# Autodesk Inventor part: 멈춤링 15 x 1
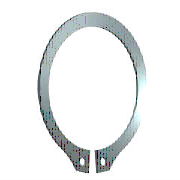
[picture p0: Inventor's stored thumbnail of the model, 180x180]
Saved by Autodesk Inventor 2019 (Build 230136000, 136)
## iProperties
IsCustomPart: 1
Created: 2012-02
Part Number: 멈춤링 15 x 1
Material: 강철, 연강
Description: 리테이닝 링(C형)
Document SubType Name: Modeling
Standard: KS B 1336
Designer: mduedu
Standards Organization: KS
Language: ko-KR
Size Designation: 15 x 1
Categories: <MemberInstance><Categories><Category DisplayName="샤프트 부품" InternalName="7f7aeb1f-a693-4053-b835-cee3144e0d98" Mnemonic="SHFT"><Category DisplayName="써클립" Inter
Density: 1 g/cm^3
Appearance: 파란색 - 벽 페인트 - 광택
Author: mduedu
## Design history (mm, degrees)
sketch "스케치1"
  geometry: L1 (-6, 0)-(6, 0) reference; L2 (0, 20.189)-(0, -80.536) reference; L3 (-48.09, 0)-(48.09, 0) reference; L4 (-0.425, -14.637)-(-0.425, -18.137); L5 (-0.425, -6.54)-(-0.425, -13.29); L6 (-2.795, 2.1)-(3.672, 2.1); L7 (0.425, -6.54)-(0.425, -13.29); L8 (0.425, -14.637)-(0.425, -18.137); C1 r 0.85 at (-1.7, -16.283); C2 r 0.85 at (1.7, -16.283); A1 r 7.15 centre (0, -7.5) between (0.425, -14.637) and (-0.425, -14.637); A2 r 9.075 centre (0, -6.975) between (4.291, -14.971) and (-4.291, -14.971); A3 r 10.646 centre (0, -7.5) between (-2.023, -17.952) and (-0.425, -18.137); A4 r 1.7 centre (-1.7, -16.283) between (-3.397, -16.376) and (-2.023, -17.952); A5 r 1.7 centre (-5.095, -16.469) between (-3.397, -16.376) and (-4.291, -14.971); A6 r 1.7 centre (5.095, -16.469) between (4.291, -14.971) and (3.397, -16.376); A7 r 1.7 centre (1.7, -16.283) between (2.023, -17.952) and (3.397, -16.376); A8 r 10.646 centre (0, -7.5) between (0.425, -18.137) and (2.023, -17.952)
  constraints: 16 point on circle, 12 end point, 10 centre point, 9 symmetric about line, 5 point on line, 4 tangent, 3 coincident, 2 horizontal, 1 perpendicular, 1 vertical, 5 other
  dimensions: "d0" = 14.3 diameter of A1 (= ND); "d1" = 3.5 distance of L4.end L4.start (= SRB2); "d6" = 0.425 distance between parallel lines of L2 L5 (= 0.25 x SD5); "d7" = 2.1 distance between parallel lines of L6 L3 (= SRB1); "d8" = 0.525 distance of A1.centre A2.centre (= 0.25 x SRB1); "d9" = 1.7 radius of A4 (= SD5); "d10" = 1.7 radius of A5 (= SD5); "d11" = 1.275 distance from line of L4 A4.centre (= 0.75 x SD5); "d12" = 1.7 diameter of C1 (= SD5); "d13" = 1.7 diameter of C2 (= SD5); "d14" = 7.5 distance from line of A1.centre L1 (= 0.5 x WD)
extrude "본체" new body sketch "스케치1" distance "d2" = 1 (= SD); taper "d3" = 0 deg
workaxis "Work Axis1"
workplane "Work Plane1"
body "Solid1"
other parameters: "WD" = 15 (= WDMIN) [user parameter; used in 1 equation term], "SD" = 1 [user parameter; used in 1 equation term], "SRB1" = 2.1 [user parameter; used in 2 equation terms], "ND" = 14.3 [user parameter; used in 1 equation term], "SRB2" = 3.5 [user parameter; used in 1 equation term], "SD5" = 1.7 [user parameter; used in 6 equation terms], "d15" = 0, "d16" = 0, "d17" = 0, "d41" = 0, "d42" = 0, "WDMIN" = 15 [user parameter; used in 1 equation term], "SD3" = 13.8 [user parameter], "WDMAX" = 16 [user parameter]
